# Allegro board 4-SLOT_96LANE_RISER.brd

Outline 322.05 x 118.24 mm; copper layers: TOP, GND, IN1, GND1, IN2, VCC, VCC1, IN3, GND2, IN4, GND3, BOTTOM. Coordinates in mm from the lower left corner of the outline.
Outline path: 0,116.24 0,34.41 0.02,34.15 arc(0.07,33.89) 0.15,33.64 0.27,33.41 0.41,33.19 arc(0.59,32.99) 0.78,32.82 1,32.68 1.23,32.56 1.48,32.48 1.74,32.42 2,32.41 167.05,32.41 167.31,32.39 167.56,32.34 167.81,32.26 168.05,32.14 168.26,31.99 168.46,31.82 168.63,31.63 168.78,31.41 168.89,31.17 168.98,30.93 169.03,30.67 169.05,30.41 169.05,15.91 169.06,15.65 169.11,15.39 169.2,15.14 169.31,14.91 arc(169.46,14.69) 169.63,14.49 169.83,14.32 arc(170.05,14.18) 170.28,14.06 170.53,13.98 170.79,13.92 171.05,13.91 193.68,13.91 194.53,13.89 194.81,13.88 195.38,13.83 195.71,13.8 196.23,13.74 196.58,13.7 197.07,13.62 197.43,13.55 197.91,13.45 198.26,13.37 198.75,13.25 199.09,13.16 199.59,13.01 200,12.88 204.36,11.43 205.18,11.18 206,10.96 206.83,10.78 207.67,10.63 208.51,10.52 209.36,10.45 210.21,10.41 210.49,10.38 arc(210.9,10.27) 211.27,10.07 211.49,9.9 211.69,9.7 211.86,9.47 211.99,9.23 212.09,8.96 212.15,8.69 212.17,8.41 212.17,0.51 212.67,0 282.87,0 283.37,0.51 283.37,7.45 arc(284.33,8.41) 285.28,7.45 285.28,0.51 285.79,0 295.96,0 296.47,0.51 296.47,7.14 arc(296.84,8.04) 297.74,8.41 320.78,8.41 arc(321,8.43) 321.21,8.48 321.41,8.58 321.59,8.7 321.75,8.86 321.88,9.04 arc(321.97,9.24) 322.03,9.46 322.05,9.68 322.05,116.97 322.03,117.2 321.97,117.41 321.88,117.61 321.75,117.79 321.59,117.95 321.41,118.07 321.21,118.17 321,118.23 320.78,118.24 2,118.24 1.74,118.23 1.48,118.18 arc(1.12,118.04) 0.78,117.83 0.59,117.66 0.41,117.46 0.27,117.24 0.15,117.01 0.07,116.76 0.02,116.51 0,116.24

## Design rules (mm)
constraint set DEFAULT: min track width 0.089

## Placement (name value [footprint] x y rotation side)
C1  -  [C0603]  56.34 90.93 270 bottom
C2  -  [C0603]  57.99 90.93 270 bottom
C3  -  [C0603]  59.64 90.93 270 top
C4  -  [C0603]  54.69 95 270 bottom
C5  -  [C0603]  56.34 95 270 bottom
C6  -  [C0603]  59.64 95 270 bottom
C7  -  [C0603]  59.64 90.93 270 bottom
C8  -  [C0603]  57.99 95 270 bottom
C9  -  [C0402_P1]  85.37 79.63 180 top
C10  -  [C0402_P1]  81.36 72.68 0 top
C11  -  [C0402_P1]  70.87 84.15 270 top
C12  -  [C0402_P1]  91.36 85.62 0 top
C13  -  [C0402_P1]  91.36 90.63 0 top
C14  -  [C0402_P1]  77.36 90.63 180 top
C15  -  [C0402_P1]  82.37 90.63 180 top
C16  -  [C0402_P1]  85.37 86.63 180 top
C17  -  [C0402_P1]  83.37 85.63 0 top
C18  -  [C0402_P1]  83.37 84.63 180 top
C19  -  [C0402_P1]  83.36 78.63 180 top
C20  -  [C0402_P1]  85.36 76.63 180 top
C21  -  [C0402_P1]  79.37 82.63 180 top
C22  -  [C0402_P1]  85.37 74.63 180 top
C23  -  [C0402]  278.84 11.94 270 bottom
C24  -  [C0402]  273.84 11.94 270 bottom
C25  -  [C0402]  269.83 11.94 270 bottom
C26  -  [C0402]  265.81 11.94 270 bottom
C27  -  [C0402]  280.34 64.39 270 bottom
C28  -  [C0402]  276.3 64.39 270 bottom
C29  -  [C0402]  272.37 64.39 270 bottom
C30  -  [C0402]  268.33 64.39 270 bottom
C31  -  [C0402]  279.33 64.39 270 bottom
C32  -  [C0402]  275.29 64.39 270 bottom
C33  -  [C0402]  271.35 64.39 270 bottom
C34  -  [C0402]  267.31 64.39 270 bottom
C35  -  [C0402]  277.83 11.94 270 bottom
C36  -  [C0402]  272.82 11.94 270 bottom
C37  -  [C0402]  268.81 11.94 270 bottom
C38  -  [C0402]  264.8 11.94 270 bottom
C39  -  [C0402]  279.48 84.71 270 bottom
C40  -  [C0402]  276.33 84.71 270 bottom
C41  -  [C0402]  272.34 84.71 270 bottom
C42  -  [C0402]  268.38 84.71 270 bottom
C43  -  [C0402]  278.46 84.71 270 bottom
C44  -  [C0402]  275.31 84.71 270 bottom
C45  -  [C0402]  271.32 84.71 270 bottom
C46  -  [C0402]  267.36 84.71 270 bottom
C47  -  [C0402]  276.05 105.03 270 bottom
C48  -  [C0402]  273.25 105.03 270 bottom
C49  -  [C0402]  269.7 105.03 270 bottom
C50  -  [C0402]  266.14 105.03 270 bottom
C51  -  [C0402]  275.03 105.03 270 bottom
C52  -  [C0402]  272.24 105.03 270 bottom
C53  -  [C0402]  268.68 105.03 270 bottom
C54  -  [C0402]  265.13 105.03 270 bottom
C55  -  [C0402]  262.33 64.39 270 bottom
C56  -  [C0402]  258.29 64.39 270 bottom
C57  -  [C0402]  254.33 64.39 270 bottom
C58  -  [C0402]  250.29 64.39 270 bottom
C59  -  [C0402]  245.26 64.39 270 bottom
C60  -  [C0402]  241.28 64.39 270 bottom
C61  -  [C0402]  237.31 64.39 270 bottom
C62  -  [C0402]  233.35 64.39 270 bottom
C63  -  [C0402]  229.31 64.39 270 bottom
C64  -  [C0402]  225.38 64.39 270 bottom
C65  -  [C0402]  220.42 64.01 0 bottom
C66  -  [C0402]  209.63 62.87 0 bottom
C67  -  [C0402]  261.32 64.39 270 bottom
C68  -  [C0402]  257.28 64.39 270 bottom
C69  -  [C0402]  253.32 64.39 270 bottom
C70  -  [C0402]  249.28 64.39 270 bottom
C71  -  [C0402]  246.28 64.39 270 bottom
C72  -  [C0402]  242.29 64.39 270 bottom
C73  -  [C0402]  238.33 64.39 270 bottom
C74  -  [C0402]  234.37 64.39 270 bottom
C75  -  [C0402]  230.33 64.39 270 bottom
C76  -  [C0402]  226.39 64.39 270 bottom
C77  -  [C0402]  220.42 65.02 0 bottom
C78  -  [C0402]  209.63 63.88 0 bottom
C79  -  [C0402]  259.82 11.94 270 bottom
C80  -  [C0402]  255.83 11.94 270 bottom
C81  -  [C0402]  251.82 11.94 270 bottom
C82  -  [C0402]  247.83 11.94 270 bottom
C83  -  [C0402]  242.83 11.94 270 bottom
C84  -  [C0402]  238.84 11.94 270 bottom
C85  -  [C0402]  234.82 11.94 270 bottom
C86  -  [C0402]  230.84 11.94 270 bottom
C87  -  [C0402]  226.82 11.94 270 bottom
C88  -  [C0402]  222.84 11.94 270 bottom
C89  -  [C0402]  218.82 11.94 270 bottom
C90  -  [C0402]  214.83 11.94 270 bottom
C91  -  [C0402]  258.8 11.94 270 bottom
C92  -  [C0402]  254.81 11.94 270 bottom
C93  -  [C0402]  250.8 11.94 270 bottom
C94  -  [C0402]  246.81 11.94 270 bottom
C95  -  [C0402]  241.81 11.94 270 bottom
C96  -  [C0402]  237.82 11.94 270 bottom
C97  -  [C0402]  233.81 11.94 270 bottom
C98  -  [C0402]  229.82 11.94 270 bottom
C99  -  [C0402]  225.81 11.94 270 bottom
C100  -  [C0402]  221.82 11.94 270 bottom
C101  -  [C0402]  217.81 11.94 270 bottom
C102  -  [C0402]  213.82 11.94 270 bottom
C103  -  [C0402]  262.33 84.71 270 bottom
C104  -  [C0402]  258.35 84.71 270 bottom
C105  -  [C0402]  254.33 84.71 270 bottom
C106  -  [C0402]  250.37 84.71 270 bottom
C107  -  [C0402]  245.31 84.71 270 bottom
C108  -  [C0402]  241.33 84.71 270 bottom
C109  -  [C0402]  237.31 84.71 270 bottom
C110  -  [C0402]  233.35 84.71 270 bottom
C111  -  [C0402]  228.35 84.71 270 bottom
C112  -  [C0402]  224.33 84.71 270 bottom
C113  -  [C0402]  218.39 85.34 0 bottom
C114  -  [C0402]  209.25 83.95 0 bottom
C115  -  [C0402]  261.32 84.71 270 bottom
C116  -  [C0402]  257.33 84.71 270 bottom
C117  -  [C0402]  253.32 84.71 270 bottom
C118  -  [C0402]  249.35 84.71 270 bottom
C119  -  [C0402]  246.33 84.71 270 bottom
C120  -  [C0402]  242.34 84.71 270 bottom
C121  -  [C0402]  238.33 84.71 270 bottom
C122  -  [C0402]  234.37 84.71 270 bottom
C123  -  [C0402]  227.33 84.71 270 bottom
C124  -  [C0402]  223.32 84.71 270 bottom
C125  -  [C0402]  218.39 84.33 0 bottom
C126  -  [C0402]  209.25 82.93 0 bottom
C127  -  [C0402]  262.36 105.03 270 bottom
C128  -  [C0402]  258.29 105.03 270 bottom
C129  -  [C0402]  254.31 105.03 270 bottom
C130  -  [C0402]  250.32 105.03 270 bottom
C131  -  [C0402]  244.35 105.03 270 bottom
C132  -  [C0402]  240.36 105.03 270 bottom
C133  -  [C0402]  236.35 105.03 270 bottom
C134  -  [C0402]  232.34 105.03 270 bottom
C135  -  [C0402]  228.35 105.03 270 bottom
C136  -  [C0402]  224.33 105.03 270 bottom
C137  -  [C0402]  220.32 105.03 270 bottom
C138  -  [C0402]  216.36 105.03 270 bottom
C139  -  [C0402]  261.34 105.03 270 bottom
C140  -  [C0402]  257.28 105.03 270 bottom
C141  -  [C0402]  253.29 105.03 270 bottom
C142  -  [C0402]  249.3 105.03 270 bottom
C143  -  [C0402]  243.33 105.03 270 bottom
C144  -  [C0402]  239.35 105.03 270 bottom
C145  -  [C0402]  235.33 105.03 270 bottom
C146  -  [C0402]  231.32 105.03 270 bottom
C147  -  [C0402]  227.33 105.03 270 bottom
C148  -  [C0402]  223.32 105.03 270 bottom
C149  -  [C0402]  219.31 105.03 270 bottom
C150  -  [C0402]  215.34 105.03 270 bottom
C151  -  [C0402]  14.68 37.34 180 top
C152  -  [C0402]  14.68 39.37 180 top
C153  -  [C0402]  14.68 41.4 180 top
C154  -  [C0402]  14.68 43.43 180 top
C155  -  [C0402]  14.68 45.47 180 top
C156  -  [C0402]  14.68 47.5 180 top
C157  -  [C0402]  14.68 49.53 180 top
C158  -  [C0402]  14.68 51.56 180 top
C159  -  [C0402]  14.05 59.56 180 top
C160  -  [C0402]  14.05 61.59 180 top
C161  -  [C0402]  14.05 63.63 180 top
C162  -  [C0402]  14.05 65.66 180 top
C163  -  [C0402]  14.05 67.69 180 top
C164  -  [C0402]  14.05 69.72 180 top
C165  -  [C0402]  14.05 71.75 180 top
C166  -  [C0402]  14.05 73.79 180 top
C167  -  [C0402]  14.68 38.35 180 top
C168  -  [C0402]  14.68 40.39 180 top
C169  -  [C0402]  14.68 42.42 180 top
C170  -  [C0402]  14.68 44.45 180 top
C171  -  [C0402]  14.68 46.48 180 top
C172  -  [C0402]  14.68 48.51 180 top
C173  -  [C0402]  14.68 50.55 180 top
C174  -  [C0402]  14.68 52.58 180 top
C175  -  [C0402]  14.05 60.58 180 top
C176  -  [C0402]  14.05 62.61 180 top
C177  -  [C0402]  14.05 64.64 180 top
C178  -  [C0402]  14.05 66.67 180 top
C179  -  [C0402]  14.05 68.71 180 top
C180  -  [C0402]  14.05 70.74 180 top
C181  -  [C0402]  14.05 72.77 180 top
C182  -  [C0402]  14.05 74.8 180 top
C183  -  [C0402]  280.34 44.07 270 bottom
C184  -  [C0402]  276.33 44.07 270 bottom
C185  -  [C0402]  272.29 44.07 270 bottom
C186  -  [C0402]  268.33 44.07 270 bottom
C187  -  [C0402]  262.36 44.07 270 bottom
C188  -  [C0402]  258.35 44.07 270 bottom
C189  -  [C0402]  254.33 44.07 270 bottom
C190  -  [C0402]  250.37 44.07 270 bottom
C191  -  [C0402]  244.35 44.07 270 bottom
C192  -  [C0402]  240.34 44.07 270 bottom
C193  -  [C0402]  236.35 44.07 270 bottom
C194  -  [C0402]  232.36 44.07 270 bottom
C195  -  [C0402]  228.35 44.07 270 bottom
C196  -  [C0402]  224.36 44.07 270 bottom
C197  -  [C0402]  217.63 44.7 0 bottom
C198  -  [C0402]  209.25 43.31 0 bottom
C199  -  [C0402]  279.33 44.07 270 bottom
C200  -  [C0402]  275.31 44.07 270 bottom
C201  -  [C0402]  271.27 44.07 270 bottom
C202  -  [C0402]  267.31 44.07 270 bottom
C203  -  [C0402]  261.34 44.07 270 bottom
C204  -  [C0402]  257.33 44.07 270 bottom
C205  -  [C0402]  253.32 44.07 270 bottom
C206  -  [C0402]  249.35 44.07 270 bottom
C207  -  [C0402]  243.33 44.07 270 bottom
C208  -  [C0402]  239.32 44.07 270 bottom
C209  -  [C0402]  235.33 44.07 270 bottom
C210  -  [C0402]  231.34 44.07 270 bottom
C211  -  [C0402]  227.33 44.07 270 bottom
C212  -  [C0402]  223.34 44.07 270 bottom
C213  -  [C0402]  217.63 43.69 0 bottom
C214  -  [C0402]  209.25 42.29 0 bottom
C215  -  [C0603]  309.83 57.66 90 bottom
C216  -  [C0402]  307.42 51.05 90 bottom
C217  -  [C0402]  308.56 56.01 270 bottom
C218  -  [C0402]  304.24 54.23 90 bottom
C219  -  [C0402]  304.24 52.45 90 bottom
C220  -  [C0402]  308.81 48.51 270 top
C221  -  [C0402]  305.51 51.05 90 bottom
C222  -  [C0402]  304.24 56.01 90 bottom
C223  -  [C0402]  309.7 33.91 90 top
C224  -  [C0603]  312.24 50.8 0 bottom
C225  -  [C0402]  310.34 51.56 90 bottom
C226  -  [C0603]  312.17 53.11 0 bottom
C227  -  [C0402]  310.34 54.36 90 bottom
C228  -  [C0805]  295.99 91.69 270 top
C229  -  [C0402]  294.59 91.69 270 top
C230  -  [C0402]  293.57 91.69 270 top
C231  -  [C0603]  286.34 91.69 270 top
C232  -  [C0402]  288.49 91.69 270 top
C233  -  [C0402]  287.48 91.69 270 top
C234  -  [C0402]  285.83 103.25 180 top
C235  -  [C0805]  295.99 71.25 270 top
C236  -  [C0402]  293.57 71.25 270 top
C237  -  [C0402]  294.59 71.25 270 top
C238  -  [C0603]  286.21 71.25 270 top
C239  -  [C0402]  288.49 71.25 270 top
C240  -  [C0402]  287.48 71.25 270 top
C241  -  [C0402]  287.22 83.57 90 top
C242  -  [C0805]  295.99 50.93 270 top
C243  -  [C0402]  294.59 50.93 270 top
C244  -  [C0402]  293.57 50.93 270 top
C245  -  [C0603]  286.21 50.93 270 top
C246  -  [C0402]  288.49 50.93 270 top
C247  -  [C0402]  287.48 50.93 270 top
C248  -  [C0402]  286.84 63.25 90 top
C249  -  [C0805]  295.99 30.61 270 top
C250  -  [C0402]  294.46 30.61 270 top
C251  -  [C0402]  293.45 30.61 270 top
C252  -  [C0603]  286.08 30.61 270 top
C253  -  [C0402]  287.35 30.61 270 top
C254  -  [C0402]  288.37 30.61 270 top
C255  -  [C0402]  286.84 43.05 90 top
C256  -  [C0402]  43.64 59.31 180 bottom
C257  -  [C0402]  305.26 56.01 270 bottom
C258  -  [C0402]  306.53 56.01 270 bottom
C259  -  [C0402]  305.89 76.2 0 bottom
C260  -  [C0402]  17.58 82.85 90 top
C261  -  [C0402]  160.05 80.92 180 top
C268  -  [C0402_P1]  83.36 86.63 180 top
C269  -  [C0402_P1]  83.37 83.63 0 top
C270  -  [C0402_P1]  83.36 82.62 180 top
C271  -  [C0402_P1]  77.37 87.63 0 top
C272  -  [C0402_P1]  83.37 76.63 180 top
C273  -  [C0402_P1]  83.36 73.63 0 top
C274  -  [C0402_P1]  79.36 85.63 0 top
C275  -  [C0402_P1]  83.36 74.63 180 top
C276  -  [C0402_P1]  79.37 84.63 180 top
C277  -  [C0402_P1]  77.37 86.63 180 top
C278  -  [C0402_P1]  77.37 84.63 180 top
C279  -  [C0402_P1]  85.37 75.63 0 top
C280  -  [C0402_P1]  85.36 84.63 180 top
C281  -  [C0402_P1]  83.36 87.63 0 top
C282  -  [C0402_P1]  83.36 80.7 180 top
C283  -  [C0402_P1]  83.37 79.63 0 top
C284  -  [C0402_P1]  81.36 71.62 180 top
C285  -  [C0402_P1]  79.36 87.62 0 top
C286  -  [C0402_P1]  71.83 91.16 270 top
C287  -  [C0402_P1]  79.37 86.63 180 top
C288  -  [C0402_P1]  70.36 70.63 180 top
C289  -  [C0402_P1]  83.36 72.63 180 top
C290  -  [C0402_P1]  83.37 77.62 0 top
C291  -  [C0402_P1]  71.86 77.13 270 top
C292  -  [C0402_P1]  83.36 75.63 0 top
C293  -  [C0402_P1]  89.85 72.17 90 top
C294  -  [C0402_P1]  85.36 82.63 180 top
C295  -  [C0402_P1]  90.86 78.13 270 top
C296  -  [C0402_P1]  77.37 85.63 0 top
C297  -  [C0402_P1]  77.36 82.63 180 top
C298  -  [C0402_P1]  79.36 90.64 180 top
C299  -  [C0402_P1]  85.37 85.63 0 top
C300  -  [C0402_P1]  85.37 73.63 0 top
C301  -  [C0402_P1]  85.36 87.63 0 top
C302  -  [C0603]  99.01 39.12 90 bottom
C303  -  [C0603]  100.41 39.12 90 bottom
C304  -  [C0603]  100.41 35.05 270 bottom
C305  -  [C0603]  99.01 35.05 270 bottom
C306  -  [C0603]  100.41 35.05 270 top
C307  -  [C0603]  99.01 35.05 270 top
C308  -  [C0603]  99.01 39.12 90 top
C309  -  [C0603]  100.41 39.12 90 top
C310  -  [C0402_P1]  84.36 90.63 180 top
C311  -  [C0402_P1]  88.35 81.62 180 top
C312  -  [C0402_P1]  75.36 90.63 180 top
C313  -  [C0402_P1]  73.37 84.63 180 top
C314  -  [C0402_P1]  73.86 88.13 90 top
C315  -  [C0402_P1]  89.36 83.63 0 top
C316  -  [C0402_P1]  89.36 87.62 0 top
C317  -  [C0402_P1]  73.37 82.63 180 top
C318  -  [C0402_P1]  87.37 71.63 0 top
C319  -  [C0402_P1]  89.37 78.63 0 top
C320  -  [C0402_P1]  89.37 75.63 0 top
C321  -  [C0402_P1]  77.36 71.63 180 top
C322  -  [C0402_P1]  73.36 77.63 180 top
C323  -  [C0402_P1]  73.36 75.63 180 top
C324  -  [C0402_P1]  73.37 89.63 180 top
C325  -  [C0402_P1]  75.37 83.63 180 top
C326  -  [C0402_P1]  84.36 88.63 0 top
C327  -  [C0402_P1]  75.37 82.63 0 top
C328  -  [C0402_P1]  75.37 84.63 180 top
C329  -  [C0402_P1]  86.36 89.63 0 top
C330  -  [C0603]  41.1 51 90 bottom
C331  -  [C0402_P1]  86.37 88.63 180 top
C332  -  [C0603]  42.62 51 90 bottom
C333  -  [C0402_P1]  88.37 89.63 0 top
C334  -  [C0603]  44.15 51 90 bottom
C335  -  [C0402_P1]  87.36 85.63 180 top
C336  -  [C0402_P1]  87.37 84.63 0 top
C337  -  [C0603]  41.1 45.26 270 bottom
C338  -  [C0402_P1]  89.36 84.63 0 top
C339  -  [C0603]  42.62 45.26 270 bottom
C340  -  [C0402_P1]  87.36 82.63 0 top
C341  -  [C0603]  44.15 45.26 270 bottom
C342  -  [C0402_P1]  89.36 85.63 0 top
C343  -  [C0402_P1]  87.36 79.63 180 top
C344  -  [C0603]  44.15 51 90 top
C345  -  [C0402_P1]  85.36 77.63 0 top
C346  -  [C0603]  44.15 45.26 270 top
C347  -  [C0402_P1]  87.36 80.7 0 top
C348  -  [C0402_P1]  75.37 87.63 180 top
C349  -  [C0402_P1]  88.86 80.13 90 top
C350  -  [C0402_P1]  75.36 79.64 180 top
C351  -  [C0402_P1]  85.36 78.63 0 top
C352  -  [C0402_P1]  75.35 80.72 180 top
C353  -  [C0402_P1]  77.36 83.63 180 top
C354  -  [C0402_P1]  75.37 85.63 180 top
C355  -  [C0402_P1]  79.37 83.64 0 top
C356  -  [C0402_P1]  87.37 74.63 0 top
C357  -  [C0402_P1]  87.37 73.63 0 top
C358  -  [C0402_P1]  87.37 72.63 0 top
C359  -  [C0402_P1]  88.85 73.14 270 top
C360  -  [C0402_P1]  73.37 83.63 180 top
C361  -  [C0402_P1]  73.36 73.62 180 top
C362  -  [C0402_P1]  85.86 72.13 270 top
C363  -  [C0402_P1]  73.36 78.63 180 top
C364  -  [C0402_P1]  87.36 77.62 180 top
C365  -  [C0402_P1]  85.36 83.63 0 top
C366  -  [C0402_P1]  87.37 75.63 0 top
C367  -  [C0402_P1]  89.37 77.62 0 top
C368  -  [C0603]  61.67 49.53 0 top
C369  -  [C0603]  108.66 35.31 270 bottom
C370  -  [C0603]  107.27 35.31 270 bottom
C371  -  [C0603]  117.68 69.22 0 top
C372  -  [C0603]  46.05 59.18 0 bottom
C373  -  [C0603]  61.67 49.53 0 bottom
C374  -  [C0603]  53.11 52.68 90 bottom
C375  -  [C0603]  53.11 52.68 90 top
C376  -  [C0402_P1]  83.37 71.63 180 top
C377  -  [C0402_P1]  79.36 71.62 180 top
C378  -  [C0603]  59.64 95 270 top
C379  -  [C0603]  42.62 51 90 top
C380  -  [C0603]  55.04 100.71 90 bottom
C381  -  [C0603]  41.1 51 90 top
C382  -  [C0603]  57.23 98.12 90 top
C383  -  [C0603]  41.1 45.26 270 top
C384  -  [C0603]  54.69 90.93 270 bottom
C385  -  [C0603]  42.62 45.26 270 top
C386  -  [C0402_P1]  82.37 89.63 0 top
C387  -  [C0402_P1]  75.36 78.62 180 top
C388  -  [C0402_P1]  82.37 88.63 180 top
C389  -  [C0402_P1]  84.87 72.12 270 top
C390  -  [C0402_P1]  81.34 87.64 0 top
C391  -  [C0402_P1]  73.37 72.64 180 top
C392  -  [C0402_P1]  81.34 83.62 0 top
C393  -  [C0402_P1]  86.36 81.64 180 top
C394  -  [C0402_P1]  81.33 84.64 180 top
C395  -  [C0402_P1]  87.36 78.63 180 top
C396  -  [C0402_P1]  81.36 78.64 180 top
C397  -  [C0402_P1]  88.36 88.64 180 top
C398  -  [C0402_P1]  81.36 80.72 180 top
C399  -  [C0402_P1]  84.36 89.62 180 top
C400  -  [C0402_P1]  81.33 85.64 0 top
C401  -  [C0402_P1]  75.37 76.63 180 top
C402  -  [C0402_P1]  81.37 74.64 180 top
C403  -  [C0402_P1]  73.36 76.63 180 top
C404  -  [C0402_P1]  77.36 74.63 0 top
C405  -  [C0402_P1]  73.37 79.62 180 top
C406  -  [C0402_P1]  79.37 73.63 180 top
C407  -  [C0402_P1]  75.37 77.63 180 top
C408  -  [C0402_P1]  81.33 86.63 180 top
C409  -  [C0402_P1]  89.37 76.63 0 top
C410  -  [C0402_P1]  81.33 82.62 180 top
C411  -  [C0402_P1]  77.37 78.63 180 top
C412  -  [C0402_P1]  81.37 79.65 0 top
C413  -  [C0402_P1]  87.37 76.62 0 top
C414  -  [C0402_P1]  81.36 73.65 0 top
C415  -  [C0402_P1]  75.37 74.64 180 top
C416  -  [C0402_P1]  81.37 76.64 180 top
C417  -  [C0402_P1]  75.36 73.63 180 top
C418  -  [C0402_P1]  81.37 75.64 0 top
C419  -  [C0402_P1]  75.36 72.63 180 top
C420  -  [C0402_P1]  77.37 75.63 180 top
C421  -  [C0402_P1]  77.36 72.64 180 top
C422  -  [C0402_P1]  79.37 89.63 0 top
C423  -  [C0402_P1]  73.37 85.63 180 top
C424  -  [C0402_P1]  77.37 76.63 0 top
C425  -  [C0402_P1]  75.36 75.63 180 top
C426  -  [C0402_P1]  79.36 74.63 0 top
C427  -  [C0402_P1]  87.36 83.63 0 top
C428  -  [C0402_P1]  79.37 88.63 180 top
C429  -  [C0402_P1]  89.36 82.62 0 top
C430  -  [C0402_P1]  85.36 80.7 180 top
C431  -  [C0402_P1]  87.37 87.63 180 top
C432  -  [C0402_P1]  81.37 77.63 0 top
C433  -  [C0402_P1]  87.37 86.63 180 top
C434  -  [C0402_P1]  79.35 80.72 0 top
C435  -  [C0402_P1]  77.36 77.63 180 top
C436  -  [C0402_P1]  79.36 79.63 180 top
C437  -  [C0402_P1]  77.36 73.63 0 top
C438  -  [C0402_P1]  79.36 78.63 0 top
C439  -  [C0402_P1]  75.37 89.63 180 top
C440  -  [C0402_P1]  79.36 77.63 180 top
C441  -  [C0402_P1]  75.37 88.63 180 top
C442  -  [C0402_P1]  79.36 76.63 0 top
C443  -  [C0402_P1]  77.37 88.63 0 top
C444  -  [C0402_P1]  79.36 75.63 180 top
C445  -  [C0402_P1]  77.36 89.64 0 top
C446  -  [C0402_P1]  77.37 79.63 0 top
C447  -  [C0402_P1]  79.36 72.63 0 top
C448  -  [C0402_P1]  77.34 80.72 180 top
C449  -  [C0402_P1]  75.37 86.63 180 top
C450  -  [C0402]  119.97 34.54 180 top
C451  -  [C0402]  121.11 40.51 90 bottom
C452  -  [C0402]  315.42 33.45 270 top
C453  -  [C0402]  281.64 71.25 90 top
C454  -  [C0402]  281.38 88.14 90 top
C455  -  [C0402]  281.76 50.93 90 top
C456  -  [C0402]  281.64 30.61 90 top
C457  -  [C0603]  75.39 91.82 180 top
C458  -  [C0402]  89.99 80.77 270 top
C459  -  [C0402]  286.21 85.98 270 top
C460  -  [C0402]  279.1 91.69 270 top
C461  -  [C0402]  285.83 45.47 270 top
C462  -  [C0402]  285.83 65.53 270 top
C463  -  [C1206]  14.3 101.09 90 top
C464  -  [C1206]  14.3 95.5 90 top
C465  -  [C0402]  18.49 100.71 0 top
C466  -  [C1206]  14.3 89.15 90 top
C467  -  [C0402]  14.3 86.36 0 top
C468  -  [C0402]  316.69 96.01 270 top
C469  -  [C0402]  22.43 80.01 90 bottom
C470  -  [C0402]  302.77 13.87 270 top
C471  -  [C0805]  298.73 90.52 180 bottom
C473  -  [C0805]  290.91 103.76 180 top
C474  -  [C0805]  284.81 91.69 270 top
C475  -  [C0805]  293.83 42.8 180 top
C476  -  [C0805]  284.43 30.61 270 top
C477  -  [C0805]  293.7 83.57 180 top
C478  -  [C0805]  284.56 50.93 270 top
C479  -  [C0805]  293.57 63.25 180 top
C480  -  [C0805]  284.56 71.25 270 top
CON1  -  [HEADER1X4S2NH_P2H2_RA]  193.63 112.78 270 top
D1  -  [LED0603]  303.28 11.33 270 top
H1  -  [HEATSINK_4P_SF41720001]  135.16 112.63 180 bottom
J1  -  [PCIE_X16D_H11]  295.83 35.25 270 top
J2  -  [PCIE_X16D_H11]  295.83 55.57 270 top
J3  -  [PCIE_X16D_H11]  295.83 75.89 270 top
J4  -  [PCIE_X16D_H11]  295.83 96.21 270 top
J5  -  [GF_PCIE_X16]  284.33 7.45 180 bottom
J6  -  [PWR2X6D2NH_P3W3H8-9_RA]  8.92 104.32 90 bottom
J7  -  [SLIVER_X8_RA]  7.84 44.15 90 bottom
J8  -  [CON_74S2H6D2S_P0-6W2-95_LDH]  7.84 70.27 90 bottom
L1  -  [B2012]  311.48 57.78 90 bottom
ME1  -  [LABEL20X4_SST21X5]  192.23 62.18 180 bottom
ME2  -  [LABEL_32X6_FULL]  271.1 111.68 180 bottom
ME3  -  [ZT_LOG_6X16]  204.67 109.37 0 top
MH1  -  [HOLE_C10D5-6B10_NPB_STANDOFF]  6 113 180 bottom
MH2  -  [GND_C10D4_6-5B10_OB5]  182.05 110 270 top
MH3  -  [GND_C10D4_6-5B10_OB5]  38 37.9 270 top
MH4  -  [GND_C10D4_6-5B10_OB5]  315.25 107 270 top
MH5  -  [GND_C10D4_6-5B10_OB5]  138 37.9 270 top
MH6  -  [GND_C10D4_6-5B10_OB5]  315.25 16.41 270 top
MH7  -  [GND_C10D4_6-5B10_OB5]  315.25 67.77 270 top
MH8  -  [HOLE_C10D5-6B10_NPB_STANDOFF]  178.05 21.41 180 bottom
NOREF  -  []  275.54 106.93 0 top
NOREF#2  -  []  271.83 86.61 0 top
NOREF#3  -  []  271.78 45.97 0 top
NOREF#4  -  []  261.82 66.29 0 top
NOREF#5  -  []  249.81 106.93 0 top
NOREF#6  -  []  195.66 52.58 90 top
NOREF#7  -  []  267.82 45.97 0 top
NOREF#8  -  []  279.83 66.29 0 top
NOREF#9  -  []  267.87 86.61 0 top
NOREF#10  -  []  257.84 86.61 0 top
NOREF#11  -  []  257.79 66.29 0 top
NOREF#12  -  []  249.86 45.97 0 top
NOREF#13  -  []  275.82 86.61 0 top
NOREF#14  -  []  192.99 52.58 90 top
NOREF#15  -  [unnamed#2]  -5 0.47 0 top
NOREF#16  -  [unnamed#2]  -5 360.19 0 top
NOREF#17  -  []  271.32 7.8 0 top
NOREF#18  -  [unnamed#2]  250.27 108.71 0 top
NOREF#19  -  []  267.82 66.29 0 top
NOREF#20  -  []  272.75 106.93 0 top
NOREF#21  -  []  18.67 -76.43 0 top
NOREF#22  -  [unnamed#2]  314.91 99.44 0 top
NOREF#23  -  []  275.79 66.29 0 top
NOREF#24  -  []  253.82 66.29 0 top
NOREF#25  -  []  198.32 49.4 90 top
NOREF#26  -  []  203.66 46.1 90 top
NOREF#27  -  []  265.63 106.93 0 top
NOREF#28  -  []  278.97 86.61 0 top
NOREF#29  -  []  261.82 86.61 0 top
NOREF#30  -  [unnamed#2]  23.7 37.59 0 top
NOREF#31  -  []  249.86 86.61 0 top
NOREF#32  -  []  261.85 106.93 0 top
NOREF#33  -  []  257.84 45.97 0 top
NOREF#34  -  []  269.19 106.93 0 top
NOREF#35  -  []  190.45 53.85 90 top
NOREF#36  -  [unnamed#2]  21.49 81.76 0 top
NOREF#37  -  []  275.82 45.97 0 top
NOREF#38  -  []  257.79 106.93 0 top
NOREF#39  -  []  253.82 86.61 0 top
NOREF#40  -  []  261.85 45.97 0 top
NOREF#41  -  []  201.12 46.23 90 top
NOREF#42  -  []  271.86 66.29 0 top
NOREF#43  -  []  195.66 49.4 90 top
NOREF#44  -  []  253.8 106.93 0 top
NOREF#45  -  []  249.79 66.29 0 top
NOREF#46  -  []  201.12 49.28 90 top
NOREF#47  -  []  253.82 45.97 0 top
NOREF#48  -  []  279.83 45.97 0 top
NOREF#49  -  [unnamed#2]  297.59 11.89 180 bottom
NOREF#50  -  [unnamed#2]  35.59 114.53 180 bottom
NOREF#51  -  [unnamed#2]  314.91 99.44 180 bottom
PC453  -  [C0402]  27.87 85.86 270 top
PC454  -  [C0402]  27.87 97.55 270 top
PC455  -  [C0603]  29.39 85.94 270 bottom
PC456  -  [C0603]  29.29 96.84 270 bottom
PC457  -  [C1206]  26.35 86.14 270 top
PC458  -  [C1206]  24.29 97.83 270 top
PC459  -  [C1206]  24.29 86.14 270 bottom
PC460  -  [C1206]  26.35 97.83 270 bottom
PC461  -  [C1206]  26.35 86.14 270 bottom
PC462  -  [C1206]  26.35 97.83 270 top
PC463  -  [C1206]  24.29 86.14 270 top
PC464  -  [C1206]  24.29 97.83 270 bottom
PC465  -  [C1206]  25.41 89.47 180 top
PC466  -  [C1206]  25.41 101.16 180 top
PC467  -  [C0402]  34.68 89.62 0 top
PC468  -  [C0402]  34.68 101.31 0 top
PC469  -  [C0603]  32.92 90.69 270 top
PC470  -  [C0603]  32.92 102.37 270 top
PC471  -  [C0402]  32.98 94.25 180 bottom
PC472  -  [C0402]  32.98 82.56 180 bottom
PC473  -  [C0603]  41.92 98.49 0 bottom
PC474  -  [C0603]  41.92 82.84 0 bottom
PC475  -  [TAJ_SX]  41.74 102.22 180 top
PC476  -  [TAJ_SX]  41.74 90.54 180 top
PC477  -  [C0603]  56.34 90.93 270 top
PC478  -  [C0603]  54.69 95 270 top
PC479  -  [C0603]  57.99 90.93 270 top
PC480  -  [C0603]  49.76 98.5 90 top
PC481  -  [C0603]  49.07 88.42 90 top
PC482  -  [C0603]  54.69 90.93 270 top
PC483  -  [C0603]  58.75 98.12 90 top
PC484  -  [C0603]  57.99 95 270 top
PC485  -  [C0603]  49.1 91.19 270 top
PC486  -  [C0603]  56.34 95 270 top
PC487  -  [C0402]  47.87 87.88 90 top
PC488  -  [C0402]  48.12 98.99 90 top
PC489  -  [C0402]  313.23 89.09 90 top
PC491  -  [C0603]  310.79 83.61 180 bottom
PC492  -  [C0603]  313.56 83.74 0 bottom
PC493  -  [C0402]  308.69 91.14 90 bottom
PC495  -  [C1206]  306.27 87.63 270 top
PC496  -  [C0603]  309.35 88.21 270 top
PC497  -  [C0402]  314.67 88.03 90 bottom
PC498  -  [C1206]  304.24 87.63 270 top
PC499  -  [C0402]  316.03 88.41 180 bottom
PC500  -  [C0402]  300.94 90.85 90 bottom
PC501  -  [C0805]  298.73 83.97 180 bottom
PC502  -  [C0402]  302.59 91.06 270 bottom
PC503  -  [C0805]  298.73 86.15 180 top
PC504  -  [C0402]  316.02 90.37 0 bottom
PC505  -  [C0805]  298.73 86.15 180 bottom
PC506  -  [C0402]  302.44 114.79 0 bottom
PC508  -  [C0603]  298.42 103.79 0 bottom
PC509  -  [C0402]  300.96 108.7 270 top
PC510  -  [C0603]  301.19 103.79 0 bottom
PC511  -  [C0402]  296.11 113.04 90 bottom
PC514  -  [C0603]  297.48 109.23 270 top
PC515  -  [C1206]  294.56 113.98 90 bottom
PC516  -  [C0402]  302.43 109.48 90 bottom
PC517  -  [C1206]  293.85 108.24 270 top
PC518  -  [C0402]  303.79 109.86 180 bottom
PC519  -  [C1206]  298.96 113.27 0 top
PC520  -  [C1206]  293.37 111.92 180 top
PC521  -  [C1206]  291.24 115.99 180 bottom
PC522  -  [C0402]  281.38 116.08 0 bottom
PC523  -  [C1206]  298.96 115.25 0 bottom
PC524  -  [C0805]  278.46 110.6 180 top
PC526  -  [C0805]  278.46 108.39 180 bottom
PC527  -  [C0402]  303.78 111.82 0 bottom
PC529  -  [C0805]  278.46 110.6 180 bottom
PC530  -  [C0805]  283.29 105.66 0 top
PC531  -  [C0805]  278.46 106.16 180 bottom
PC532  -  [C0402]  288.08 116.34 0 bottom
PC533  -  [C0805]  282.02 114.68 0 bottom
PC534  -  [C0402]  116.36 39.11 90 bottom
PC535  -  [C0805]  113.84 37.02 180 bottom
PC536  -  [C0402]  111.17 40.03 180 top
PC537  -  [C0402]  108.52 39.41 90 bottom
PC538  -  [C0805]  109.94 39.24 90 bottom
PC539  -  [C0402]  79.68 39.73 90 bottom
PC541  -  [C0603]  82.12 34.37 0 top
PC542  -  [C0603]  79.35 34.37 180 top
PC543  -  [C0402]  84.79 41.22 90 top
PC545  -  [C1206]  87.93 40.49 0 top
PC546  -  [C0603]  83.11 38.01 270 bottom
PC547  -  [C0402]  78.24 38.66 90 top
PC548  -  [C1206]  81.4 41.54 180 top
PC549  -  [C0402]  76.88 39.05 0 top
PC550  -  [C1206]  81.36 41.66 180 bottom
PC551  -  [C0402]  90.73 40.34 90 top
PC552  -  [C0603]  94.82 39.5 90 top
PC553  -  [C0402]  89.49 40.26 0 bottom
PC554  -  [C0603]  94.82 35.18 270 top
PC555  -  [C0402]  76.89 41 180 top
PC556  -  [C0603]  93.42 35.18 270 top
PC557  -  [C0603]  93.42 39.5 90 top
PC558  -  [C0603]  18.5 99.54 0 top
PC559  -  [EC_F80_H8]  19.53 91.64 180 top
PC560  -  [C0402]  22.76 106.78 180 top
PC561  -  [C0402]  21.41 108.36 90 top
PC562  -  [C0402]  22.78 108.73 180 top
PC563  -  [C0402]  23.95 101.98 90 bottom
PC564  -  [C0402]  15.29 114.1 90 top
PC565  -  [C0603]  25.2 102.15 90 bottom
PC566  -  [C0402]  17.65 114.1 90 top
PC567  -  [C0402]  22.03 112.07 90 top
PC568  -  [C0603]  21.41 114.68 90 top
PC569  -  [C0402]  31.19 102.45 90 bottom
PC570  -  [C0402]  30.66 108.16 90 top
PC571  -  [C0603]  29.98 101.85 90 bottom
PC572  -  [C0603]  18.87 114.68 90 top
PC573  -  [C0402]  16.31 114.1 90 top
PC574  -  [C0402]  23.75 91 90 bottom
PC575  -  [C0603]  25.2 90.47 90 bottom
PC576  -  [C0402]  22.08 110.71 0 top
PC577  -  [C0402]  31.19 90.64 90 bottom
PC578  -  [C0402]  35.81 108.36 90 bottom
PC579  -  [C0603]  29.98 90.16 90 bottom
PC580  -  [C0402]  71.2 37.07 0 top
PC581  -  [C0603]  66.38 47.31 0 top
PC582  -  [C0402]  71.45 42.29 90 bottom
PC583  -  [C0603]  69.15 47.31 0 top
PC584  -  [C0402]  64.71 38.32 270 top
PC585  -  [C1206]  67.55 35.86 0 top
PC586  -  [C1206]  59.83 35.12 180 top
PC587  -  [C0603]  66.24 43.56 90 bottom
PC588  -  [C1206]  62.45 42.87 90 bottom
PC589  -  [C0402]  71.02 41.63 270 top
PC591  -  [C0402]  72.4 41.46 180 top
PC592  -  [C0402]  51.89 50.55 0 top
PC593  -  [C0402]  54.95 34.94 0 top
PC594  -  [C0805]  46.61 42.29 180 top
PC595  -  [C0805]  47.45 43.48 270 bottom
PC596  -  [C0805]  51.72 46.35 0 bottom
PC597  -  [C0402]  72.4 38.62 270 top
PC598  -  [C0805]  51.89 49.02 0 top
PC599  -  [C0805]  46.61 44.45 180 top
PC600  -  [C0805]  49.35 43.48 270 bottom
PC612  -  [C0805]  278.46 106.16 180 top
PC613  -  [C0805]  283.25 107.58 0 top
PC614  -  [C0805]  278.46 103.92 180 top
PC615  -  [C0805]  278.46 108.39 180 top
PC620  -  [C1206]  305.87 91.77 180 bottom
PC621  -  [C1206]  311.48 91.74 0 top
PC623  -  [C0805]  298.73 88.34 180 top
PC660  -  [TAJ_SX]  46.2 93.27 180 bottom
PC661  -  [TAJ_SX]  48.24 83.62 270 bottom
PC700  -  [C0603]  19.64 103.12 90 top
PC701  -  [C0603]  16.64 104.8 180 top
PC1523  -  [C1206]  298.96 113.18 0 bottom
PC1531  -  [C0805]  282 115 0 top
PC1533  -  [C0805]  283.25 109.43 0 top
PC1585  -  [C1206]  61.96 39.18 180 bottom
PC1586  -  [C1206]  67.55 38.98 0 bottom
PC1588  -  [C1206]  63.16 36.87 270 top
PC1589  -  [C1206]  67.55 37.92 0 top
PC1592  -  [C0603]  46.74 46.23 180 bottom
PC1594  -  [C0603]  51.72 44.7 0 bottom
PC1595  -  [C0603]  50.62 36.83 0 top
PC1596  -  [C0805]  51.72 48.26 0 bottom
PC1598  -  [C0805]  46.61 40.13 180 top
PC1599  -  [C0805]  46.61 37.97 180 top
PC1600  -  [C0805]  51.72 50.16 0 bottom
PC1621  -  [C1206]  311.48 91.31 0 bottom
PC1623  -  [C0805]  298.73 88.34 180 bottom
PC2531  -  [C0805]  281.99 111.29 0 top
PC2533  -  [C0805]  282 113.14 0 top
PC2596  -  [C0603]  46.61 36.32 180 top
PL2  -  [IND_PA4390_SMPM91X130_4P]  41.92 96.52 0 top
PL3  -  [IND_PA4390_SMPM91X130_4P]  41.92 84.84 0 top
PL4  -  [IND_PCMC063T]  304.55 86.51 180 bottom
PL5  -  [B2012]  303.53 91.03 180 top
PL6  -  [IND_PCMB104T]  287.22 108.58 180 bottom
PL7  -  [B2012]  287.22 114.94 180 top
PL8  -  [IND_PCMB053T]  88.34 36.32 0 top
PL9  -  [B2012]  86.44 40.36 0 bottom
PL10  -  [B2012]  18.65 97.91 0 top
PL11  -  [IND_PCMB104T]  55.73 42.84 180 top
PL12  -  [B2012]  287.21 114.94 180 bottom
PL20  -  [B2012]  55.81 36.36 180 top
PL510  -  [B2012]  18.65 96.06 0 top
PQ6  -  [SOT363]  32.61 107.82 0 top
PQ7  -  [SOT363]  32.97 107.8 0 bottom
PR143  -  [R0402]  35.92 89.07 270 bottom
PR295  -  [R0402]  34.63 87.77 180 bottom
PR296  -  [R0402]  35.92 100.75 270 bottom
PR297  -  [R0402]  34.63 99.45 180 bottom
PR298  -  [R0402]  34.55 100.93 180 bottom
PR299  -  [R0402]  34.55 89.24 180 bottom
PR300  -  [R0603]  35.52 91.15 180 top
PR301  -  [R0603]  35.52 102.83 180 top
PR302  -  [R0402]  33.25 87.95 270 bottom
PR303  -  [R0402]  33.25 99.63 270 bottom
PR304  -  [R0603]  31.58 90.69 270 top
PR305  -  [R0603]  31.58 102.37 270 top
PR306  -  [R0805]  34.78 95.03 270 bottom
PR307  -  [R0805]  34.78 83.35 270 bottom
PR308  -  [R0402]  41.43 96.94 90 bottom
PR309  -  [R0402]  41.43 84.39 270 bottom
PR310  -  [R0402]  42.42 96.94 90 bottom
PR311  -  [R0402]  42.42 84.39 270 bottom
PR314  -  [R0402]  314.86 84.06 90 top
PR315  -  [R0402]  315.85 84.57 90 top
PR317  -  [R0402]  319 86.51 270 bottom
PR320  -  [R0402]  311.71 86.06 90 top
PR321  -  [R0402]  313.21 87.35 270 top
PR322  -  [R0402]  315.19 85.67 90 bottom
PR323  -  [R0603]  313.97 85.62 0 top
PR324  -  [R0603]  311.99 82.37 90 top
PR325  -  [R0402]  317.37 87.27 0 bottom
PR326  -  [R0402]  315.93 88.09 90 top
PR327  -  [R0402]  314.67 89.78 90 bottom
PR328  -  [R0402]  316.02 89.4 0 bottom
PR329  -  [R0603]  300.13 92.53 180 top
PR330  -  [R0805]  298.73 90.67 180 top
PR332  -  [R0402]  302.74 114.32 270 top
PR333  -  [R0402]  302.43 113.8 0 bottom
PR336  -  [R0402]  303.76 104.93 180 bottom
PR339  -  [R0402]  303.63 106.55 0 bottom
PR340  -  [R0603]  301.73 107.07 0 top
PR341  -  [R0603]  299.72 103.77 180 top
PR342  -  [R0402]  303.78 108.87 0 bottom
PR343  -  [R0402]  299.82 107.28 270 top
PR344  -  [R0402]  302.44 108.61 90 top
PR345  -  [R0402]  302.26 104.47 0 top
PR346  -  [R0402]  302.43 111.23 90 bottom
PR347  -  [R0402]  303.78 110.86 0 bottom
PR348  -  [R0603]  305.13 115.19 90 top
PR353  -  [R0402]  115.05 37.64 90 top
PR355  -  [R0402]  111.36 39.74 90 bottom
PR356  -  [R0402]  109.79 39.8 90 top
PR357  -  [R0402]  74.75 35.64 0 bottom
PR361  -  [R0402]  75.87 36.75 0 bottom
PR363  -  [R0402]  75.13 36.04 270 top
PR366  -  [R0402]  80.87 36.5 90 bottom
PR367  -  [R0402]  79.7 37.99 270 bottom
PR368  -  [R0402]  78.25 36.93 90 top
PR369  -  [R0603]  78.94 36.25 180 bottom
PR370  -  [R0603]  79.94 34.29 0 bottom
PR371  -  [R0402]  75.36 38.05 180 top
PR372  -  [R0402]  77.19 38.13 90 bottom
PR373  -  [R0402]  78.24 40.41 90 top
PR374  -  [R0402]  76.89 40.04 180 top
PR375  -  [R0603]  96.22 39.5 270 top
PR376  -  [R0402]  52.02 101.93 180 top
PR377  -  [R0603]  52.55 100.83 180 bottom
PR378  -  [R0402]  52.02 101.04 180 top
PR382  -  [R0402]  22.75 105.79 0 top
PR383  -  [R0402]  21.41 106.62 90 top
PR385  -  [R0402]  17.96 107.26 270 bottom
PR387  -  [R0402]  22.76 107.77 0 top
PR389  -  [R0402]  16.94 108 90 bottom
PR390  -  [R0402]  15.01 112.32 0 bottom
PR391  -  [R0402]  18.72 114.27 270 bottom
PR392  -  [R0402]  17.73 114.27 270 bottom
PR393  -  [R0402]  13.54 112.42 90 top
PR394  -  [R0402]  13.08 107.67 90 top
PR395  -  [R0402]  13.08 110.35 270 top
PR396  -  [R0402]  12.69 109.01 0 top
PR397  -  [R0603]  16.23 109.6 180 bottom
PR398  -  [R0402]  28.76 106.98 0 top
PR399  -  [R0402]  32.01 106 0 top
PR400  -  [R0603]  20.14 114.68 90 top
PR401  -  [R0402]  16.25 114.2 90 bottom
PR402  -  [R0402]  34.59 108.13 270 top
PR403  -  [R0402]  34.11 105.33 180 top
PR404  -  [R0402]  15.26 114.2 90 bottom
PR405  -  [R0402]  33.35 109.6 180 bottom
PR406  -  [R0402]  30.89 106.63 270 bottom
PR407  -  [R0603]  33.45 105.87 0 bottom
PR408  -  [R0402]  19.25 110.72 90 bottom
PR409  -  [R0402]  22.08 109.72 0 top
PR410  -  [R0402]  20.27 110.72 90 bottom
PR411  -  [R0402]  21.64 110.77 90 bottom
PR413  -  [R0402]  35.21 107.01 0 bottom
PR414  -  [R0402]  34.82 108.36 90 bottom
PR418  -  [R0402]  71.34 36.79 90 bottom
PR420  -  [R0402]  71.84 46.79 180 top
PR423  -  [R0402]  72 43.37 270 top
PR424  -  [R0603]  70.22 44.57 0 bottom
PR426  -  [R0603]  66.77 47.81 0 bottom
PR427  -  [R0402]  73.84 42.46 0 top
PR428  -  [R0402]  68.34 44.77 90 bottom
PR429  -  [R0402]  68.78 41.66 0 bottom
PR430  -  [R0402]  69.6 47.33 0 bottom
PR431  -  [R0402]  71.02 39.88 270 top
PR432  -  [R0402]  73.46 39.64 270 top
PR433  -  [R0402]  40.59 47.24 0 top
PR434  -  [R0402]  37.86 47.48 180 bottom
PR435  -  [R0402]  37.86 46.46 180 bottom
PR503  -  [R0603]  52.55 102.16 180 bottom
PR504  -  [R0402]  68.78 43.43 180 bottom
PR505  -  [R0402]  39.93 45.44 270 top
PR800  -  [R0402]  21.29 103.25 0 top
PR801  -  [R0402]  17.1 103.63 180 top
PU13  -  [QFN40_NCP5339]  32.11 85.43 270 top
PU15  -  [QFN40_NCP5339]  32.11 97.12 270 top
PU16  -  [PQFN16_IR3823]  311.43 88.9 270 bottom
PU17  -  [PQFN17_IR3895]  297.69 108.35 270 bottom
PU18  -  [SON6E_D65_D8]  113.86 39.6 90 bottom
PU19  -  [PQFN16_IR3823]  81.48 39.53 270 top
PU20  -  [WDFN6_P0-65H0-8_EP]  27.59 102.05 90 bottom
PU21  -  [QFN28_P0-5_EPAD]  17.27 109.57 270 top
PU22  -  [WDFN6_P0-65H0-8_EP]  27.59 90.36 90 bottom
PU23  -  [PQFN17_IR3895]  66.28 42.76 90 top
Q1  -  [SOT23_GDS]  168.99 110.74 180 top
Q2  -  [SOT23_GDS]  168.99 114.17 180 top
Q3  -  [SOT23_GDS]  314.91 48.64 180 top
Q4  -  [SOT23_GDS]  314.91 52.83 180 top
Q5  -  [SOT23]  314.4 96.01 0 top
Q6  -  [SOT23]  20.27 79.76 270 bottom
Q7  -  [SOT23_GDS]  300.56 12.8 270 top
Q13  -  [SOT23_GDS]  293.32 87.5 180 top
Q14  -  [SOT23_GDS]  293.32 67.18 180 top
Q15  -  [SOT23_GDS]  293.32 46.86 180 top
Q16  -  [SOT23_GDS]  289.13 87.5 180 top
Q17  -  [SOT23_GDS]  289.13 67.18 180 top
Q18  -  [SOT23_GDS]  289.26 46.86 180 top
Q19  -  [SOT23_GDS]  315.29 26.42 270 top
Q20  -  [SOT23_GDS]  124.79 36.85 90 top
Q21  -  [SOT23_GDS]  293.32 26.54 180 top
Q22  -  [SOT23_GDS]  311.1 26.42 270 top
Q23  -  [SOT23_GDS]  124.79 40.92 270 top
Q24  -  [SOT23_GDS]  289.13 26.54 180 top
Q25  -  [SOT23]  15.42 83.24 180 top
R1  -  [R0402]  312.12 50.93 180 top
R2  -  [R0402]  312.12 51.94 0 top
R3  -  [R0402]  316.05 50.67 180 top
R4  -  [R0402]  312.12 53.09 180 top
R5  -  [R0402]  285.83 43.05 270 top
R6  -  [R0402]  285.83 63.25 270 top
R7  -  [R0402]  286.21 83.57 270 top
R8  -  [R0402]  283.54 103.25 0 top
R9  -  [R0402]  294.72 11.94 90 top
R10  -  [R0402]  104.47 66.55 180 top
R11  -  [R0402]  59.56 53.55 0 top
R12  -  [R0402]  59.89 50.93 0 top
R13  -  [R0402]  55.2 57.91 180 bottom
R14  -  [R0402]  81.31 70.59 180 top
R15  -  [R0402]  59.89 52.27 0 bottom
R16  -  [R0402]  59.89 50.93 0 bottom
R17  -  [R0402]  58.9 105.54 0 bottom
R18  -  [R0402]  59.89 54.84 0 bottom
R19  -  [R0402]  307.16 43.56 90 top
R20  -  [R0402]  306.02 43.56 90 top
R21  -  [R0402]  304.88 43.56 90 top
R22  -  [R0402]  303.1 43.56 90 top
R23  -  [R0402]  302.59 45.85 90 top
R24  -  [R0402]  301.45 43.56 90 top
R25  -  [R0402]  300.31 43.56 90 top
R26  -  [R0402]  299.16 43.56 90 top
R27  -  [R0402]  300.69 31.24 270 top
R28  -  [R0402]  301.83 31.24 270 top
R29  -  [R0402]  302.97 28.83 270 top
R30  -  [R0402]  304.12 31.24 270 top
R31  -  [R0402]  107.65 87.5 180 top
R32  -  [R0402]  120.47 91.31 180 top
R33  -  [R0402]  113.74 77.85 180 top
R34  -  [R0402]  120.22 74.04 180 top
R35  -  [R0402]  104.47 87.5 180 top
R36  -  [R0402]  120.47 89.41 180 top
R37  -  [R0402]  104.47 75.95 180 top
R38  -  [R0402]  104.47 72.14 180 top
R39  -  [R0402]  104.47 79.76 180 top
R40  -  [R0402]  110.69 72.14 180 top
R41  -  [R0402]  109.81 70.28 180 top
R42  -  [R0402]  107.65 70.23 180 top
R43  -  [R0402]  83.36 70.41 180 top
R44  -  [R0402]  116.92 72.14 180 top
R45  -  [R0402]  120.22 72.14 180 top
R46  -  [R0402]  107.65 66.42 180 top
R47  -  [R0402]  85.37 69.42 180 top
R48  -  [R0402]  113.74 70.23 180 top
R49  -  [R0402]  70.44 74.42 180 top
R50  -  [R0402]  52.63 106.68 0 bottom
R51  -  [R0402]  58.9 110.74 0 bottom
R52  -  [R0402]  58.9 109.73 0 bottom
R53  -  [R0402]  55.2 56.64 180 bottom
R54  -  [R0402]  52.63 105.54 0 bottom
R55  -  [R0402]  52.63 107.7 0 bottom
R56  -  [R0402]  52.63 109.73 0 bottom
R57  -  [R0402]  58.9 107.7 0 bottom
R58  -  [R0402]  58.9 108.71 0 bottom
R59  -  [R0402]  52.63 110.74 0 bottom
R60  -  [R0402]  52.63 112.78 0 bottom
R61  -  [R0402]  52.63 113.79 0 bottom
R62  -  [R0402]  52.63 108.71 0 bottom
R63  -  [R0402]  58.9 111.76 0 bottom
R64  -  [R0402]  58.9 113.79 0 bottom
R65  -  [R0402]  52.63 114.81 0 bottom
R66  -  [R0402]  52.63 111.76 0 bottom
R67  -  [R0402]  110.69 95.12 180 top
R68  -  [R0402]  110.69 93.22 180 top
R69  -  [R0402]  107.65 91.31 180 top
R70  -  [R0402]  107.65 89.41 180 top
R71  -  [R0402]  107.65 95.12 180 top
R72  -  [R0402]  107.65 93.22 180 top
R73  -  [R0402]  104.47 91.31 180 top
R74  -  [R0402]  104.47 89.41 180 top
R75  -  [R0402]  113.62 91.31 180 top
R76  -  [R0402]  303.61 48.77 90 top
R77  -  [R0402]  307.8 48.51 90 top
R78  -  [R0402]  308.43 45.85 270 top
R79  -  [R0402]  306.66 31.24 90 top
R80  -  [R0402]  305.64 31.24 270 top
R81  -  [R0402]  309.45 45.85 270 top
R82  -  [R0402]  309.45 43.56 270 top
R83  -  [R0402]  310.59 45.85 270 top
R84  -  [R0402]  310.59 43.56 270 top
R85  -  [R0402]  290.02 12.45 90 bottom
R86  -  [R0402]  291.92 12.45 90 bottom
R87  -  [R0402]  307.8 31.24 90 top
R88  -  [R0402]  308.81 31.24 90 top
R89  -  [R0402]  314.45 56.66 180 top
R90  -  [R0402]  314.45 57.81 180 top
R91  -  [R0402]  312.17 54.38 180 bottom
R92  -  [R0402]  312.17 49.55 180 bottom
R93  -  [R0402]  293.96 85.34 0 top
R94  -  [R0402]  294.08 65.02 0 top
R95  -  [R0402]  307.16 45.85 270 top
R96  -  [R0402]  306.02 45.85 270 top
R97  -  [R0402]  304.88 45.85 270 top
R98  -  [R0402]  303.73 45.85 270 top
R99  -  [R0402]  300.81 47.88 0 top
R100  -  [R0402]  301.45 45.85 270 top
R101  -  [R0402]  300.31 45.85 270 top
R102  -  [R0402]  299.16 45.85 270 top
R103  -  [R0402]  300.69 28.83 90 top
R104  -  [R0402]  301.83 28.83 90 top
R105  -  [R0402]  303.86 27.05 180 top
R106  -  [R0402]  304.12 28.83 90 top
R107  -  [R0402]  293.96 44.7 0 top
R108  -  [R0402]  290.91 85.34 180 top
R109  -  [R0402]  300.97 10.16 0 top
R110  -  [R0402]  303.91 13.87 90 top
R111  -  [R0402]  56.47 49.73 180 bottom
R112  -  [R0402]  63.1 50.99 0 top
R113  -  [R0402]  69.8 77.85 180 top
R114  -  [R0402]  35.26 62.61 0 bottom
R115  -  [R0402]  55.45 52.78 0 top
R116  -  [R0402]  59.11 58.8 0 bottom
R117  -  [R0402]  81.61 69.34 90 top
R118  -  [R0402]  308.13 59.18 90 top
R119  -  [R0402]  307.11 59.18 90 top
R120  -  [R0402]  305.94 59.18 90 top
R121  -  [R0402]  304.93 59.18 90 top
R122  -  [R0402]  301.58 55.12 180 top
R123  -  [R0402]  301.58 54.1 180 top
R124  -  [R0402]  301.58 52.96 180 top
R125  -  [R0402]  301.58 51.94 180 top
R126  -  [R0402]  304.52 48.77 270 top
R127  -  [R0402]  305.41 48.77 270 top
R128  -  [R0402]  56.47 51 180 top
R129  -  [R0402]  56.47 49.73 0 top
R130  -  [R0402]  109.93 65.41 180 bottom
R131  -  [R0402]  109.93 64.52 0 bottom
R132  -  [R0402]  110.69 68.33 180 top
R133  -  [R0402]  107.65 68.33 0 top
R134  -  [R0402]  120.22 75.95 180 top
R135  -  [R0402]  116.92 75.95 0 top
R136  -  [R0402]  57.26 58.75 0 top
R137  -  [R0402]  104.47 74.04 180 top
R138  -  [R0402]  57.26 56.18 0 bottom
R139  -  [R0402]  47.21 54.1 180 bottom
R140  -  [R0402]  47.21 55.37 0 bottom
R141  -  [R0402]  120.47 87.5 180 top
R142  -  [R0402]  110.69 77.85 180 top
R143  -  [R0402]  48.85 62.48 180 bottom
R144  -  [R0402]  298.53 28.83 90 top
R145  -  [R0402]  299.54 28.83 90 top
R146  -  [R0402]  51.02 54.1 180 bottom
R147  -  [R0402]  123.39 77.85 180 top
R148  -  [R0402]  110.69 74.04 180 top
R149  -  [R0402]  50.75 62.48 0 bottom
R150  -  [R0402]  51.02 54.1 180 top
R151  -  [R0402]  51.02 56.64 180 bottom
R152  -  [R0402]  290.78 65.02 180 top
R153  -  [R0402]  291.03 44.7 180 top
R154  -  [R0402]  294.21 89.79 180 top
R155  -  [R0402]  294.21 69.47 180 top
R156  -  [R0402]  294.21 49.15 180 top
R157  -  [R0402]  290.4 89.79 180 top
R158  -  [R0402]  290.4 69.47 180 top
R159  -  [R0402]  290.53 49.15 180 top
R160  -  [R0402]  316.1 29.36 180 top
R161  -  [R0402]  122.12 34.54 0 top
R162  -  [R0402]  293.83 24.38 0 top
R163  -  [R0402]  312.24 29.34 180 top
R164  -  [R0402]  104.47 70.23 180 top
R165  -  [R0402]  55.2 55.24 180 bottom
R166  -  [R0402]  113.74 74.04 180 top
R167  -  [R0402]  113.74 72.14 180 top
R168  -  [R0402]  56.47 51 180 bottom
R169  -  [R0402]  62.94 50.93 0 bottom
R170  -  [R0402]  51.02 52.83 180 top
R171  -  [R0402]  51.02 52.83 180 bottom
R172  -  [R0402]  55.5 59.21 180 top
R173  -  [R0402]  55.5 57.94 0 top
R174  -  [R0402]  59.89 53.54 180 bottom
R175  -  [R0402]  57.26 53.64 180 top
R176  -  [R0402]  77.7 69.47 270 top
R177  -  [R0402]  63.11 52.46 0 top
R178  -  [R0402]  63.57 53.72 180 top
R179  -  [R0402]  51.02 56.64 180 top
R180  -  [R0402]  51.02 55.37 0 top
R181  -  [R0402]  110.69 66.42 180 top
R182  -  [R0402]  113.74 66.42 0 top
R183  -  [R0402]  169.24 82.93 180 top
R184  -  [R0402]  169.24 81.92 180 top
R185  -  [R0402]  305.13 28.83 90 top
R186  -  [R0402]  305.51 27.05 0 top
R187  -  [R0402]  55.2 54.05 180 bottom
R188  -  [R0402]  59.89 54.84 0 top
R189  -  [R0402]  57.95 56.21 0 top
R190  -  [R0402]  55.2 54.05 180 top
R191  -  [R0402]  125.05 43.43 0 top
R192  -  [R0402]  290.78 24.38 180 top
R193  -  [R0402]  315.47 31.39 270 top
R194  -  [R0402]  122.51 35.94 90 top
R195  -  [R0402]  283.41 91.69 90 top
R196  -  [R0402]  282.4 91.69 90 top
R197  -  [R0402]  214.33 103.63 180 top
R198  -  [R0402]  214.33 83.19 180 top
R199  -  [R0402]  214.2 62.99 180 top
R200  -  [R0402]  213.18 43.05 180 top
R201  -  [R0402]  57.97 55.09 0 top
R202  -  [R0402]  70.94 72.14 90 top
R203  -  [R0402]  294.21 28.83 180 top
R204  -  [R0402]  310.9 31.26 270 top
R205  -  [R0402]  55.72 55.23 180 top
R206  -  [R0402]  104.47 67.56 180 top
R207  -  [R0402]  47.21 56.64 180 bottom
R208  -  [R0402]  47.96 52.22 180 top
R209  -  [R0402]  122.51 41.27 270 top
R210  -  [R0402]  290.4 28.83 180 top
R211  -  [R0402]  116.66 35.43 270 top
R212  -  [R0402]  283.54 83.57 270 top
R213  -  [R0402]  282.53 83.57 270 top
R214  -  [R0402]  284.81 63.25 270 top
R215  -  [R0402]  283.8 63.25 270 top
R216  -  [R0402]  284.81 43.05 270 top
R217  -  [R0402]  107.65 74.04 180 top
R218  -  [R0402]  107.65 79.76 180 top
R219  -  [R0402]  115.25 69.34 0 top
R220  -  [R0402]  106.38 64.52 180 bottom
R221  -  [R0402]  283.8 43.05 270 top
R222  -  [R0402]  292.43 69.47 0 top
R223  -  [R0402]  288.62 69.47 0 top
R224  -  [R0402]  292.43 89.79 0 top
R225  -  [R0402]  288.62 89.79 0 top
R226  -  [R0402]  292.43 49.15 0 top
R227  -  [R0402]  288.75 49.15 0 top
R228  -  [R0402]  292.43 28.83 0 top
R229  -  [R0402]  58.9 112.78 0 bottom
R230  -  [R0402]  47.22 55.37 180 top
R231  -  [R0402]  64.59 105.41 270 bottom
R232  -  [R0402]  58.9 106.68 0 bottom
R233  -  [R0402]  288.62 28.83 0 top
R234  -  [R0402]  122.51 37.72 270 top
R235  -  [R0402]  122.51 39.5 90 top
R236  -  [R0402]  314.15 29.34 0 top
R237  -  [R0402]  310.47 29.34 180 top
R238  -  [R0402]  287.61 103.25 0 top
R239  -  [R0402]  291.54 91.69 90 top
R240  -  [R0402]  290.53 91.69 90 top
R241  -  [R0402]  117.04 87.5 180 top
R242  -  [R0402]  110.69 87.5 180 top
R243  -  [R0402]  117.04 91.31 180 top
R244  -  [R0402]  117.04 89.41 180 top
R245  -  [R0402]  289.51 91.69 90 top
R246  -  [R0402]  292.56 91.69 90 top
R247  -  [R0402]  288.24 83.57 270 top
R248  -  [R0402]  291.54 71.25 90 top
R249  -  [R0402]  290.53 71.25 90 top
R250  -  [R0402]  289.51 71.25 90 top
R251  -  [R0402]  292.56 71.25 90 top
R252  -  [R0402]  287.86 63.25 270 top
R253  -  [R0402]  58.9 114.81 0 bottom
R254  -  [R0402]  66.5 105.41 270 bottom
R255  -  [R0402]  110.69 97.03 180 top
R256  -  [R0402]  113.62 95.12 180 top
R257  -  [R0402]  291.54 50.93 90 top
R258  -  [R0402]  290.53 50.93 90 top
R259  -  [R0402]  289.51 50.93 90 top
R260  -  [R0402]  292.56 50.93 90 top
R261  -  [R0402]  287.86 43.05 270 top
R262  -  [R0402]  291.42 30.61 90 top
R263  -  [R0402]  290.4 30.61 90 top
R264  -  [R0402]  289.38 30.61 90 top
R265  -  [R0402]  110.69 89.41 180 top
R266  -  [R0402]  113.62 93.22 180 top
R267  -  [R0402]  110.69 91.31 180 top
R268  -  [R0402]  104.47 97.03 180 bottom
R269  -  [R0402]  57.26 57.48 180 top
R270  -  [R0402]  62.78 55.26 270 top
R271  -  [R0402]  55.45 52.78 0 bottom
R272  -  [R0402]  35.26 61.47 0 bottom
R273  -  [R0402]  35.26 63.63 0 bottom
R274  -  [R0402]  35.26 64.64 0 bottom
R275  -  [R0402]  292.43 30.61 90 top
R276  -  [R0402]  166.45 113.03 270 top
R277  -  [R0402]  120.09 40.51 90 bottom
R278  -  [R0402]  119.08 40.51 90 bottom
R279  -  [R0402]  311.99 33.45 270 top
R280  -  [R0402]  313.13 33.45 270 top
R281  -  [R0402]  315.16 45.97 270 top
R282  -  [R0402]  315.16 43.69 90 top
R283  -  [R0402]  313.89 45.97 270 top
R284  -  [R0402]  313.89 43.69 90 top
R285  -  [R0402]  312.62 45.97 270 top
R286  -  [R0402]  312.62 43.69 90 top
R287  -  [R0402]  57.26 58.75 0 bottom
R288  -  [R0402]  57.26 57.48 180 bottom
R289  -  [R0402]  57.26 54.91 0 bottom
R290  -  [R0402]  57.26 53.64 180 bottom
R291  -  [R0402]  120.22 77.85 180 top
R292  -  [R0402]  116.92 77.85 0 top
R293  -  [R0402]  314.28 31.37 90 top
R294  -  [R0402]  314.28 33.45 270 top
R295  -  [R0402]  113.74 79.76 180 top
R296  -  [R0402]  117.68 35.43 90 top
R297  -  [R0402]  316.31 43.69 90 top
R298  -  [R0402]  316.31 45.97 90 top
R299  -  [R0402]  313.26 77.34 180 bottom
R300  -  [R0402]  313.26 78.36 180 bottom
R301  -  [R0402]  313.26 79.38 180 bottom
R302  -  [R0402]  302.34 79.63 0 bottom
R303  -  [R0402]  162.51 81.23 90 top
R304  -  [R0402]  161.49 81.23 90 top
R305  -  [R0402]  282.14 86.36 270 bottom
R306  -  [R0402]  282.4 45.85 270 bottom
R307  -  [R0402]  281.38 89.53 180 bottom
R308  -  [R0402]  282.53 65.91 270 bottom
R309  -  [R0402]  284.68 45.72 180 bottom
R318  -  [R0402]  55.42 56.64 0 top
R319  -  [R0402]  116.92 74.04 0 top
R320  -  [R0402]  42.9 53.85 180 top
R321  -  [R0402]  113.62 89.41 0 top
R322  -  [R0402]  104.47 95.12 0 top
R323  -  [R0402]  104.47 93.22 0 top
R324  -  [R0402]  59.93 52.08 0 top
R325  -  [R0402]  110.69 79.76 180 top
R326  -  [R0402]  107.65 77.85 180 top
R327  -  [R0402]  104.47 77.85 0 top
R328  -  [R0402]  110.69 75.95 180 top
R329  -  [R0402]  107.65 75.95 0 top
R330  -  [R0402]  120.22 79.76 180 top
R331  -  [R0402]  116.92 79.76 0 top
R332  -  [R0402]  113.62 87.5 180 top
R333  -  [R0402]  44.76 53.82 180 top
R334  -  [R0402]  104.47 68.48 180 top
R335  -  [R0402]  113.74 75.95 180 top
R343  -  [R0402]  51.02 55.37 180 bottom
R344  -  [R0402]  107.65 72.14 180 top
R345  -  [R0402]  123.39 79.76 180 top
R346  -  [R0402]  113.74 68.33 0 top
R348  -  [R0402]  166.45 111.12 270 top
R349  -  [R0402]  282.91 90.3 0 top
R350  -  [R0402]  283.16 71.25 270 top
R351  -  [R0402]  163.22 106.45 0 top
R352  -  [R0402]  283.16 50.93 270 top
R353  -  [R0402]  282.91 30.61 270 top
SHORT1  -  [SHORT0805]  278.08 116.2 180 top
